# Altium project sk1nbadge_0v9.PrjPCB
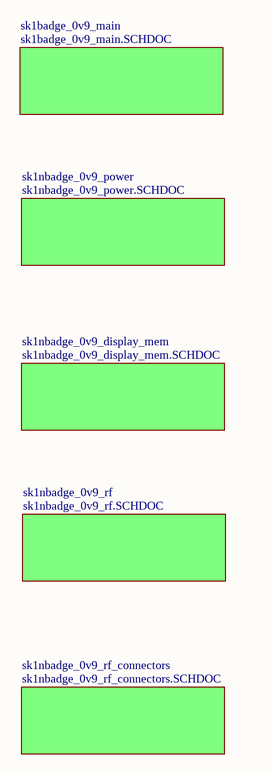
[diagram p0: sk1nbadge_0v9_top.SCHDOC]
6 sheets, 198 parts. Net scope: global (net labels, ports and power ports of the same name join across sheets).
Board file: sk1nbadge_pcb_0v9.pcbdoc
Sheets:
  sk1nbadge_0v9_top.SCHDOC
    sk1badge_0v9_main = sk1badge_0v9_main.SCHDOC
    sk1nbadge_0v9_power = sk1nbadge_0v9_power.SCHDOC
    sk1nbadge_0v9_display_mem = sk1nbadge_0v9_display_mem.SCHDOC
    sk1nbadge_0v9_rf = sk1nbadge_0v9_rf.SCHDOC
    sk1nbadge_0v9_rf_connectors = sk1nbadge_0v9_rf_connectors.SCHDOC

## Sheet sk1nbadge_0v9_top.SCHDOC
size Letter

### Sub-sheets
sk1badge_0v9_main = sk1badge_0v9_main.SCHDOC: no entries
sk1nbadge_0v9_display_mem = sk1nbadge_0v9_display_mem.SCHDOC: no entries
sk1nbadge_0v9_power = sk1nbadge_0v9_power.SCHDOC: no entries
sk1nbadge_0v9_rf = sk1nbadge_0v9_rf.SCHDOC: no entries
sk1nbadge_0v9_rf_connectors = sk1nbadge_0v9_rf_connectors.SCHDOC: no entries

## Sheet sk1badge_0v9_main.SCHDOC
size Letter
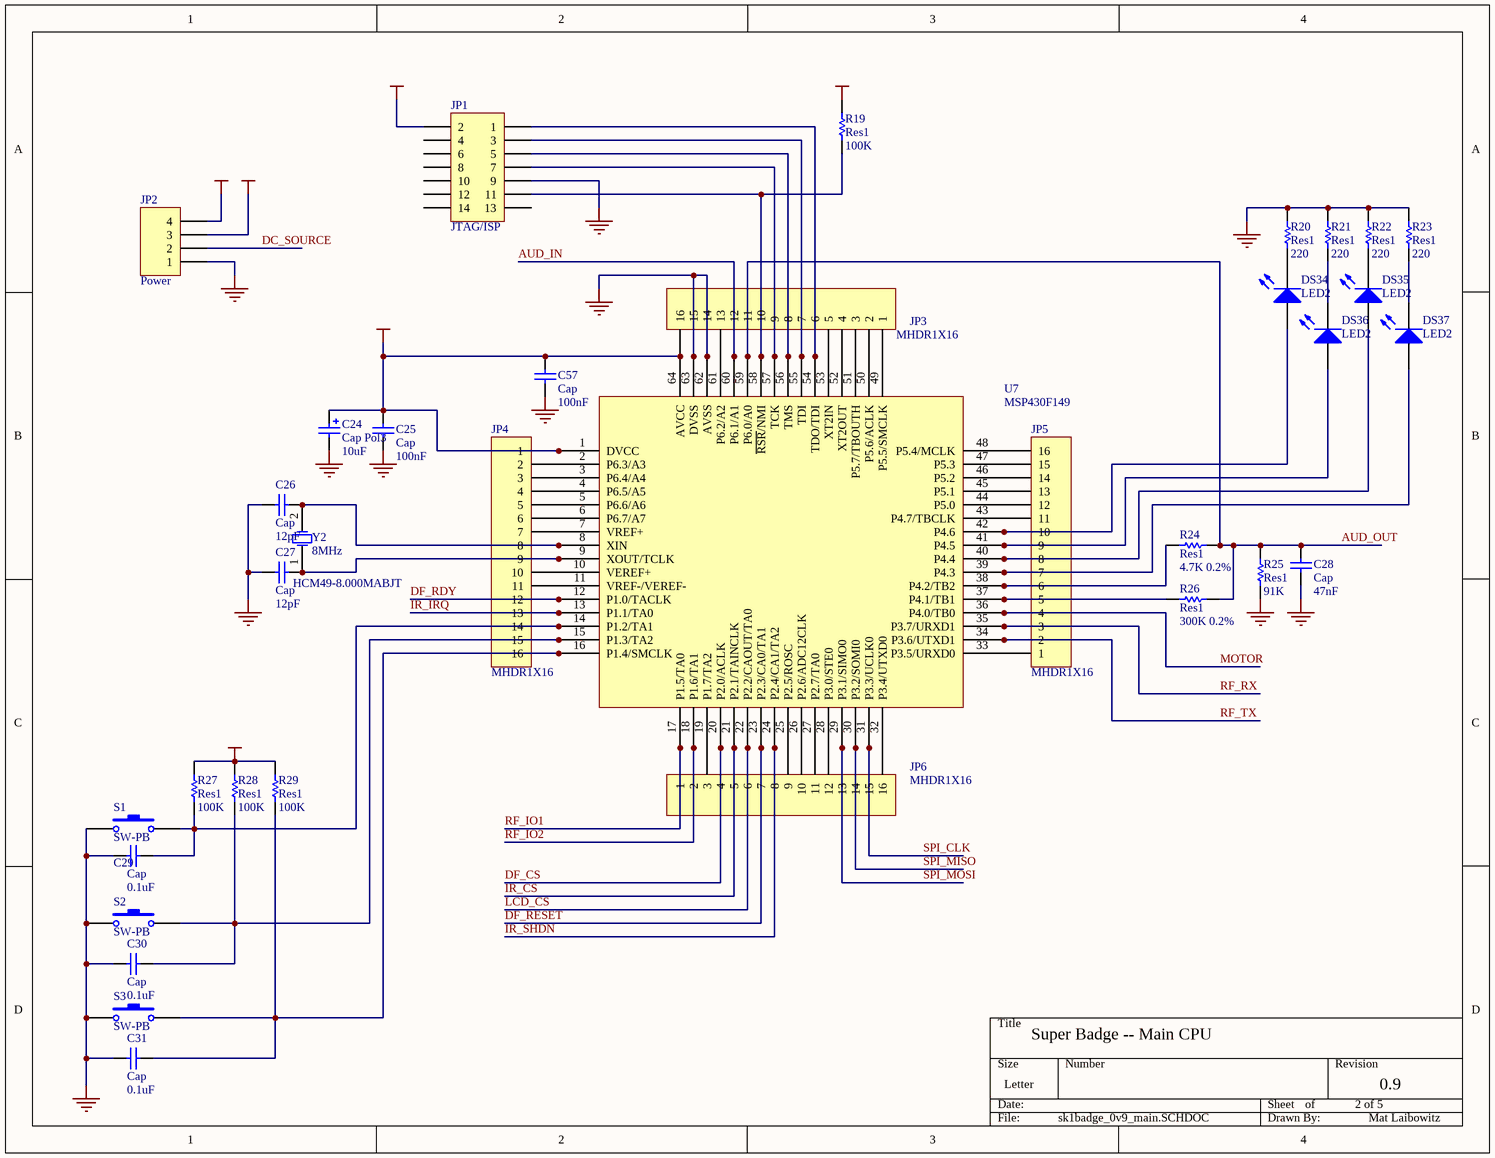
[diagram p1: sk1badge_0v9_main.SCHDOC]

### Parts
C24  Cap Pol3  value 10uF  [6032-28]
C25  Cap  value 100nF  [0402]
C26  Cap  value 12pF  [0402]
C27  Cap  value 12pF  [0402]
C28  Cap  value 47nF  [0402]
C29  Cap  value 0.1uF  [0402]
C30  Cap  value 0.1uF  [0402]
C31  Cap  value 0.1uF  [0402]
C57  Cap  value 100nF  [0402]
DS34  LED2  [LED-1206]
DS35  LED2  [LED-1206]
DS36  LED2  [LED-1206]
DS37  LED2  [LED-1206]
JP1  JTAG/ISP  [HDR2X7]
JP2  Power  [HDR1X4]
JP3  MHDR1X16  [MHDR1X16]
JP4  MHDR1X16  [MHDR1X16]
JP5  MHDR1X16  [MHDR1X16]
JP6  MHDR1X16  [MHDR1X16]
R19  Res1  value 100K  [0402]
R20  Res1  value 220  [0402]
R21  Res1  value 220  [0402]
R22  Res1  value 220  [0402]
R23  Res1  value 220  [0402]
R24  Res1  value 4.7K 0.2%  [0402]
R25  Res1  value 91K  [0402]
R26  Res1  value 300K 0.2%  [0402]
R27  Res1  value 100K  [0402]
R28  Res1  value 100K  [0402]
R29  Res1  value 100K  [0402]
S1  SW-PB  [B3S-1000]
S2  SW-PB  [B3S-1000]
S3  SW-PB  [B3S-1000]
U7  MSP430F149  [QFP64]
Y2  8MHz  PART: HCM49-8.000MABJT  [HCM49]

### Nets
3.3V: C24.1 C25.1 C57.1 JP1.2 JP2.3 JP3.16 JP4.1 R19.2 R27.2 R28.2 R29.2 U7.1(DVCC) U7.64(AVCC)
5V: JP2.4
GND: C24.2 C25.2 C26.1 C27.1 C28.1 C29.1 C30.1 C31.1 C57.2 JP1.9 JP2.1 JP3.14 JP3.15 R20.2 R21.2 R22.2 R23.2 R25.1 S1.1 S2.1 S3.1 U7.62(AVSS) U7.63(DVSS)
AUD_IN: JP3.12 U7.60(P6.1/A1)
AUD_OUT: C28.2 JP3.11 R24.2 R25.2 R26.2 U7.59(P6.0/A0)
DC_SOURCE: JP2.2
DF_CS: JP6.4 U7.20(P2.0/ACLK)
DF_RDY: JP4.12 U7.12(P1.0/TACLK)
DF_RESET: JP6.7 U7.23(P2.3/CA0/TA1)
IR_CS: JP6.5 U7.21(P2.1/TAINCLK)
IR_IRQ: JP4.13 U7.13(P1.1/TA0)
IR_SHDN: JP6.8 U7.24(P2.4/CA1/TA2)
LCD_CS: JP6.6 U7.22(P2.2/CAOUT/TA0)
MOTOR: JP5.4 U7.36(P4.0/TB0)
RF_IO1: JP6.1 U7.17(P1.5/TA0)
RF_IO2: JP6.2 U7.18(P1.6/TA1)
RF_RX: JP5.3 U7.35(P3.7/URXD1)
RF_TX: JP5.2 U7.34(P3.6/UTXD1)
SPI_CLK: JP6.15 U7.31(P3.3/UCLK0)
SPI_MISO: JP6.14 U7.30(P3.2/SOMI0)
SPI_MOSI: JP6.13 U7.29(P3.1/SIMO0)
NetC26_2: C26.2 JP4.8 U7.8(XIN) Y2.2(OSC2)
NetC27_2: C27.2 JP4.9 U7.9(XOUT/TCLK) Y2.1(OSC1)
NetC29_2: C29.2 JP4.14 R27.1 S1.2 U7.14(P1.2/TA1)
NetC30_2: C30.2 JP4.15 R28.1 S2.2 U7.15(P1.3/TA2)
NetC31_2: C31.2 JP4.16 R29.1 S3.2 U7.16(P1.4/SMCLK)
NetDS34_1: DS34.1(A) JP5.10 U7.42(P4.6)
NetDS34_2: DS34.2(K) R20.1
NetDS35_1: DS35.1(A) JP5.8 U7.40(P4.4)
NetDS35_2: DS35.2(K) R22.1
NetDS36_1: DS36.1(A) JP5.9 U7.41(P4.5)
NetDS36_2: DS36.2(K) R21.1
NetDS37_1: DS37.1(A) JP5.7 U7.39(P4.3)
NetDS37_2: DS37.2(K) R23.1
NetJP1_1: JP1.1 JP3.6 U7.54(TDO/TDI)
NetJP1_3: JP1.3 JP3.7 U7.55(TDI)
NetJP1_5: JP1.5 JP3.8 U7.56(TMS)
NetJP1_7: JP1.7 JP3.9 U7.57(TCK)
NetJP1_11: JP1.11 JP3.10 R19.1 U7.58(~{RSR}/NMI)
NetJP3_1: JP3.1 U7.49(P5.5/SMCLK)
NetJP3_2: JP3.2 U7.50(P5.6/ACLK)
NetJP3_3: JP3.3 U7.51(P5.7/TBOUTH)
NetJP3_4: JP3.4 U7.52(XT2OUT)
NetJP3_5: JP3.5 U7.53(XT2IN)
NetJP3_13: JP3.13 U7.61(P6.2/A2)
NetJP4_2: JP4.2 U7.2(P6.3/A3)
NetJP4_3: JP4.3 U7.3(P6.4/A4)
NetJP4_4: JP4.4 U7.4(P6.5/A5)
NetJP4_5: JP4.5 U7.5(P6.6/A6)
NetJP4_6: JP4.6 U7.6(P6.7/A7)
NetJP4_7: JP4.7 U7.7(VREF+)
NetJP4_10: JP4.10 U7.10(VEREF+)
NetJP4_11: JP4.11 U7.11(VREF-/VEREF-)
NetJP5_1: JP5.1 U7.33(P3.5/URXD0)
NetJP5_5: JP5.5 R26.1 U7.37(P4.1/TB1)
NetJP5_6: JP5.6 R24.1 U7.38(P4.2/TB2)
NetJP5_11: JP5.11 U7.43(P4.7/TBCLK)
NetJP5_12: JP5.12 U7.44(P5.0)
NetJP5_13: JP5.13 U7.45(P5.1)
NetJP5_14: JP5.14 U7.46(P5.2)
NetJP5_15: JP5.15 U7.47(P5.3)
NetJP5_16: JP5.16 U7.48(P5.4/MCLK)
NetJP6_3: JP6.3 U7.19(P1.7/TA2)
NetJP6_9: JP6.9 U7.25(P2.5/ROSC)
NetJP6_10: JP6.10 U7.26(P2.6/ADC12CLK)
NetJP6_11: JP6.11 U7.27(P2.7/TA0)
NetJP6_12: JP6.12 U7.28(P3.0/STE0)
NetJP6_16: JP6.16 U7.32(P3.4/UTXD0)

Not connected (* = marked no-connect by the designer): JP1 4 6 8 10 12 13 14

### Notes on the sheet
- Super Badge -- Main CPU
- 2 of 5
- 0.9
- Mat Laibowitz

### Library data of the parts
C24 = Cap Pol3: Polarized Capacitor (Surface Mount); Manufacturer: Generic Components; Class I: Passive
C25-C31 C57 = Cap: Capacitor; Manufacturer: Generic Components; Class I: Passive
DS34-DS37 = LED2: Typical RED, GREEN, YELLOW, AMBER GaAs LED; Manufacturer: Generic Components; Class I: Optoelectronic
JP1 = Header 7X2: Header, 7-Pin, Dual row; Manufacturer: Generic Components; Class I: Connector
JP2 = Header 4: Header, 4-Pin; Manufacturer: Generic Components; Class I: Connector
JP3-JP6 = MHDR1X16: Header, 16-Pin; Manufacturer: Generic Components; Class I: Connector
R19-R29 = Res1: Resistor; Manufacturer: Generic Components; Class I: Passive
S1-S3 = SW-PB: Switch; Manufacturer: Generic Components
Y2 = XTAL: Crystal Oscillator; Manufacturer: Generic Components

## Sheet sk1nbadge_0v9_power.SCHDOC: sk1n Badge -- Power and Audio Sections
size Letter; DrawnBy: Mat Laibowitz; SheetNumber: 3; SheetTotal: 5
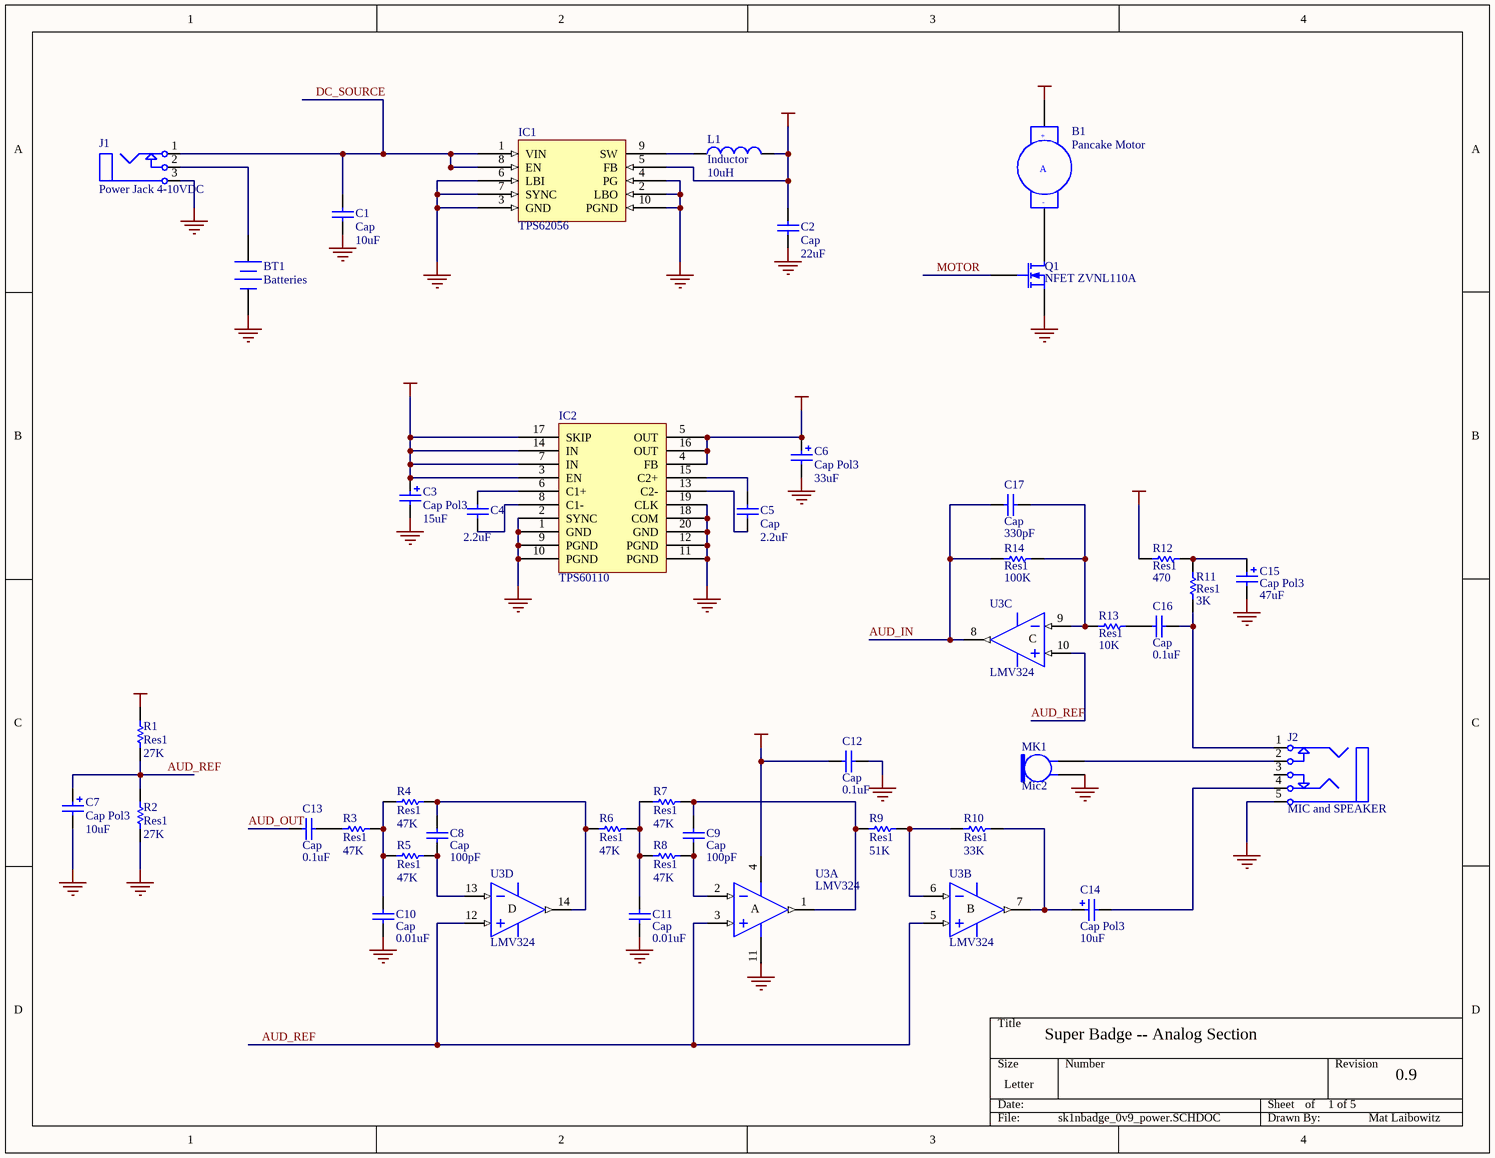
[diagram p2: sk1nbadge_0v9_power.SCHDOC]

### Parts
B1  Pancake Motor  [PANCAKE_MOTOR]
BT1  Batteries  [BAT-2]
C1  Cap  value 10uF  [6032-28]
C2  Cap  value 22uF  [6032-28]
C3  Cap Pol3  value 15uF  [6032-28]
C4  value 2.2uF  [1206]
C5  Cap  value 2.2uF  [1206]
C6  Cap Pol3  value 33uF  [6032-28]
C7  Cap Pol3  value 10uF  [6032-28]
C8  Cap  value 100pF  [0402]
C9  Cap  value 100pF  [0402]
C10  Cap  value 0.01uF  [0402]
C11  Cap  value 0.01uF  [0402]
C12  Cap  value 0.1uF  [0402]
C13  Cap  value 0.1uF  [0402]
C14  Cap Pol3  value 10uF  [6032-28]
C15  Cap Pol3  value 47uF  [6032-28]
C16  Cap  value 0.1uF  [0402]
C17  Cap  value 330pF  [0402]
IC1  (no value)  [MSOP10]
IC2  TPS60110  [TSOP/PWP/20]
J1  Power Jack 4-10VDC  [PJ-002A]
J2  MIC and SPEAKER  [SJ-3535N]
L1  Inductor  value 10uH  [DN4835]
MK1  Mic2  [MIC54B]
Q1  NFET ZVNL110A  [BCY-W3/H.8]
R1  Res1  value 27K  [0402]
R2  Res1  value 27K  [0402]
R3  Res1  value 47K  [0402]
R4  Res1  value 47K  [0402]
R5  Res1  value 47K  [0402]
R6  Res1  value 47K  [0402]
R7  Res1  value 47K  [0402]
R8  Res1  value 47K  [0402]
R9  Res1  value 51K  [0402]
R10  Res1  value 33K  [0402]
R11  Res1  value 3K  [0402]
R12  Res1  value 470  [0402]
R13  Res1  value 10K  [0402]
R14  Res1  value 100K  [0402]
U3  LMV324  [TSSOP14]  (parts A,B,C,D of 4)

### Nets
3.3V: B1.1(+) C2.2 C3.1 C12.1 IC1.5(FB) IC2.3(EN) IC2.7(IN) IC2.14(IN) IC2.17(SKIP) L1.2 R1.2 R12.1 U3.4(V+)
5V: C6.1 IC2.4(FB) IC2.5(OUT) IC2.16(OUT)
GND: BT1.2(-) C1.1 C2.1 C3.2 C6.2 C7.2 C10.1 C11.1 C12.2 C15.2 IC1.2(LBO) IC1.3(GND) IC1.4(PG) IC1.6(LBI) IC1.7(SYNC) IC1.10(PGND) IC2.1(GND) IC2.2(SYNC) IC2.9(PGND) IC2.10(PGND) IC2.11(PGND) IC2.12(PGND) IC2.18(COM) IC2.19(CLK) IC2.20(GND) J1.3(C) J2.5(E) MK1.1 Q1.3(S) R2.1 U3.11(V-)
AUD_IN: C17.1 R14.1 U3.8(OUT)
AUD_OUT: C13.1
AUD_REF: C7.1 R1.1 R2.2 U3.3(IN+) U3.5(IN+) U3.10(IN+) U3.12(IN+)
DC_SOURCE: C1.2 IC1.1(VIN) IC1.8(EN) J1.1(A)
MOTOR: Q1.2(G)
NetB1_2: B1.2(-) Q1.1(D)
NetBT1_1: BT1.1(+) J1.2(B)
NetC4_1: C4.1 IC2.6(C1+)
NetC4_2: C4.2 IC2.8(C1-)
NetC5_1: C5.1 IC2.13(C2-)
NetC5_2: C5.2 IC2.15(C2+)
NetC8_1: C8.1 R5.2 U3.13(IN-)
NetC8_2: C8.2 R4.2 R6.1 U3.14(OUT)
NetC9_1: C9.1 R8.2 U3.2(IN-)
NetC9_2: C9.2 R7.2 R9.1 U3.1(OUT)
NetC10_2: C10.2 R3.2 R4.1 R5.1
NetC11_2: C11.2 R6.2 R7.1 R8.1
NetC13_2: C13.2 R3.1
NetC14_1: C14.1 R10.2 U3.7(OUT)
NetC14_2: C14.2 J2.4(D)
NetC15_1: C15.1 R11.2 R12.2
NetC16_1: C16.1 R13.2
NetC16_2: C16.2 J2.1(A) R11.1
NetC17_2: C17.2 R13.1 R14.2 U3.9(IN-)
NetIC1_9: IC1.9(SW) L1.1
NetJ2_2: J2.2(B) MK1.2
NetR9_2: R9.2 R10.1 U3.6(IN-)

Not connected (* = marked no-connect by the designer): J2 3(C)

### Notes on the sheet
- Super Badge -- Analog Section
- 1 of 5
- 0.9
- Mat Laibowitz

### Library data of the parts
B1 = Motor Servo: Servo Motor; Manufacturer: Generic Components
BT1 = Battery: Multicell Battery; Manufacturer: Generic Components
C1 C2 C4 C5 C8-C13 C16 C17 = Cap: as C25 on sheet sk1badge_0v9_main
C3 C6 C7 C14 C15 = Cap Pol3: as C24 on sheet sk1badge_0v9_main
IC1 = TPS62056: TI STEP DOWN CONVERTER
IC2 = TPS60110: TI CHARGE PUMP DC/DC CONVERTER
J1 = Phonejack: 2-Conductor Jack with 1 break contact; Manufacturer: Generic Components; Class I: Connector
J2 = Phonejack Stero SW: 3-Conductor Jack with 2 break contacts (normals) and 1 auxiliary make contact; Manufacturer: Generic Components; Class I: Connector
L1 = Inductor: Manufacturer: Generic Components; Class I: Passive
MK1 = Mic2: Microphone; Manufacturer: Generic Components
Q1 = MOSFET-N: N-Channel MOSFET; Manufacturer: Generic Components; Class I: Discrete; Class II: MOSFET - Low Power
R1-R14 = Res1: as R19 on sheet sk1badge_0v9_main
U3 = LMV324: Quad Low Voltage Op Amp; Manufacturer: Analog Devices; Class I: Amplifier; Class II: Operational Amplifier

## Sheet sk1nbadge_0v9_display_mem.SCHDOC
size Letter
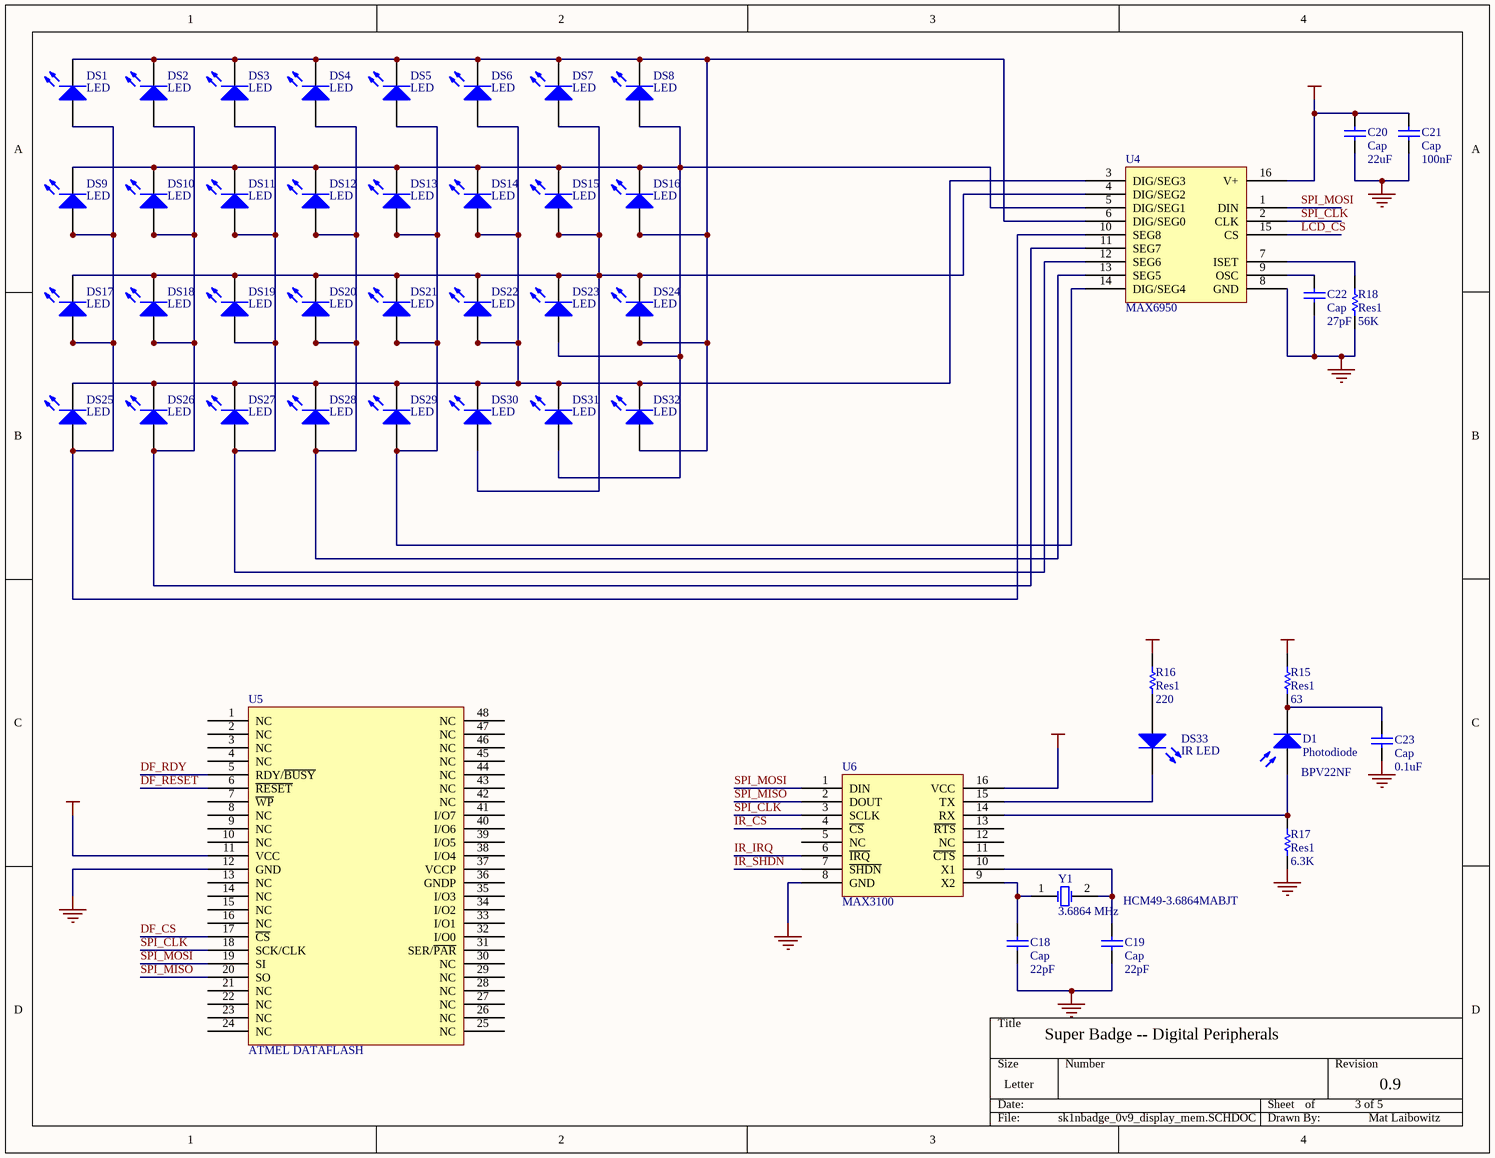
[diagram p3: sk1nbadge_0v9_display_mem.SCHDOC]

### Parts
C18  Cap  value 22pF  [0402]
C19  Cap  value 22pF  [0402]
C20  Cap  value 22uF  [1206]
C21  Cap  value 100nF  [0402]
C22  Cap  value 27pF  [0402]
C23  Cap  value 0.1uF  [0402]
D1  Photodiode  PART: BPV22NF  [PIN2]
DS1  LED  [LED-1206]
DS2  LED  [LED-1206]
DS3  LED  [LED-1206]
DS4  LED  [LED-1206]
DS5  LED  [LED-1206]
DS6  LED  [LED-1206]
DS7  LED  [LED-1206]
DS8  LED  [LED-1206]
DS9  LED  [LED-1206]
DS10  LED  [LED-1206]
DS11  LED  [LED-1206]
DS12  LED  [LED-1206]
DS13  LED  [LED-1206]
DS14  LED  [LED-1206]
DS15  LED  [LED-1206]
DS16  LED  [LED-1206]
DS17  LED  [LED-1206]
DS18  LED  [LED-1206]
DS19  LED  [LED-1206]
DS20  LED  [LED-1206]
DS21  LED  [LED-1206]
DS22  LED  [LED-1206]
DS23  LED  [LED-1206]
DS24  LED  [LED-1206]
DS25  LED  [LED-1206]
DS26  LED  [LED-1206]
DS27  LED  [LED-1206]
DS28  LED  [LED-1206]
DS29  LED  [LED-1206]
DS30  LED  [LED-1206]
DS31  LED  [LED-1206]
DS32  LED  [LED-1206]
DS33  IR LED  [PIN2]
R15  Res1  value 63  [0402]
R16  Res1  value 220  [0402]
R17  Res1  value 6.3K  [0402]
R18  Res1  value 56K  [0402]
U4  MAX6950  [QSOP16]
U5  ATMEL DATAFLASH  [TSSOP48/DF]
U6  MAX3100  [QSOP16]
Y1  3.6864 MHz  PART: HCM49-3.6864MABJT  [HCM49]

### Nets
3.3V: C20.2 C21.2 R15.2 R16.2 U4.16(V+) U5.11(VCC) U6.16(VCC)
GND: C18.1 C19.1 C20.1 C21.1 C22.1 C23.1 R17.1 R18.1 U4.8(GND) U5.12(GND) U6.8(GND)
DF_CS: U5.17(~{CS})
DF_RDY: U5.5(RDY/~{BUSY})
DF_RESET: U5.6(~{RESET})
IR_CS: U6.4(~{CS})
IR_IRQ: U6.6(~{IRQ})
IR_SHDN: U6.7(~{SHDN})
LCD_CS: U4.15(CS)
SPI_CLK: U4.2(CLK) U5.18(SCK/CLK) U6.3(SCLK)
SPI_MISO: U5.20(SO) U6.2(DOUT)
SPI_MOSI: U4.1(DIN) U5.19(SI) U6.1(DIN)
NetC18_2: C18.2 U6.9(X2) Y1.1(OSC1)
NetC19_2: C19.2 U6.10(X1) Y1.2(OSC2)
NetC22_2: C22.2 U4.9(OSC)
NetC23_2: C23.2 D1.2(K) R15.1
NetD1_1: D1.1(A) R17.2 U6.14(RX)
NetDS1_1: DS1.1(A) DS9.1(A) DS17.1(A) DS25.1(A) U4.10(SEG8)
NetDS1_2: DS1.2(K) DS2.2(K) DS3.2(K) DS4.2(K) DS5.2(K) DS6.2(K) DS7.2(K) DS8.2(K) DS16.1(A) DS24.1(A) DS32.1(A) U4.6(DIG/SEG0)
NetDS2_1: DS2.1(A) DS10.1(A) DS18.1(A) DS26.1(A) U4.11(SEG7)
NetDS3_1: DS3.1(A) DS11.1(A) DS19.1(A) DS27.1(A) U4.12(SEG6)
NetDS4_1: DS4.1(A) DS12.1(A) DS20.1(A) DS28.1(A) U4.13(SEG5)
NetDS5_1: DS5.1(A) DS13.1(A) DS21.1(A) DS29.1(A) U4.14(DIG/SEG4)
NetDS6_1: DS6.1(A) DS14.1(A) DS22.1(A) DS25.2(K) DS26.2(K) DS27.2(K) DS28.2(K) DS29.2(K) DS30.2(K) DS31.2(K) DS32.2(K) U4.3(DIG/SEG3)
NetDS7_1: DS7.1(A) DS15.1(A) DS17.2(K) DS18.2(K) DS19.2(K) DS20.2(K) DS21.2(K) DS22.2(K) DS23.2(K) DS24.2(K) DS30.1(A) U4.4(DIG/SEG2)
NetDS8_1: DS8.1(A) DS9.2(K) DS10.2(K) DS11.2(K) DS12.2(K) DS13.2(K) DS14.2(K) DS15.2(K) DS16.2(K) DS23.1(A) DS31.1(A) U4.5(DIG/SEG1)
NetDS33_1: DS33.1(A) R16.1
NetDS33_2: DS33.2(K) U6.15(TX)
NetR18_2: R18.2 U4.7(ISET)

Not connected (* = marked no-connect by the designer): U5 1(NC) 2(NC) 3(NC) 4(NC) 7(~{WP}) 8(NC) 9(NC) 10(NC) 13(NC) 14(NC) 15(NC) 16(NC) 21(NC) 22(NC) 23(NC) 24(NC) 25(NC) 26(NC) 27(NC) 28(NC) 29(NC) 30(NC) 31(SER/~{PAR}) 32(I/O0) 33(I/O1) 34(I/O2) 35(I/O3) 36(GNDP) 37(VCCP) 38(I/O4) 39(I/O5) 40(I/O6) 41(I/O7) 42(NC) 43(NC) 44(NC) 45(NC) 46(NC) 47(NC) 48(NC); U6 5(NC) 11(~{CTS}) 12(NC) 13(~{RTS})

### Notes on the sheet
- Super Badge -- Digital Peripherals
- 3 of 5
- 0.9
- Mat Laibowitz

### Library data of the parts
C18-C23 = Cap: as C25 on sheet sk1badge_0v9_main
D1 = Photo Sen: Photosensitive Diode; Manufacturer: Generic Components; Class I: Optoelectronic
DS1-DS33 = LED2: as DS34 on sheet sk1badge_0v9_main
R15-R18 = Res1: as R19 on sheet sk1badge_0v9_main
Y1 = XTAL: as Y2 on sheet sk1badge_0v9_main

## Sheet sk1nbadge_0v9_rf.SCHDOC
size Letter
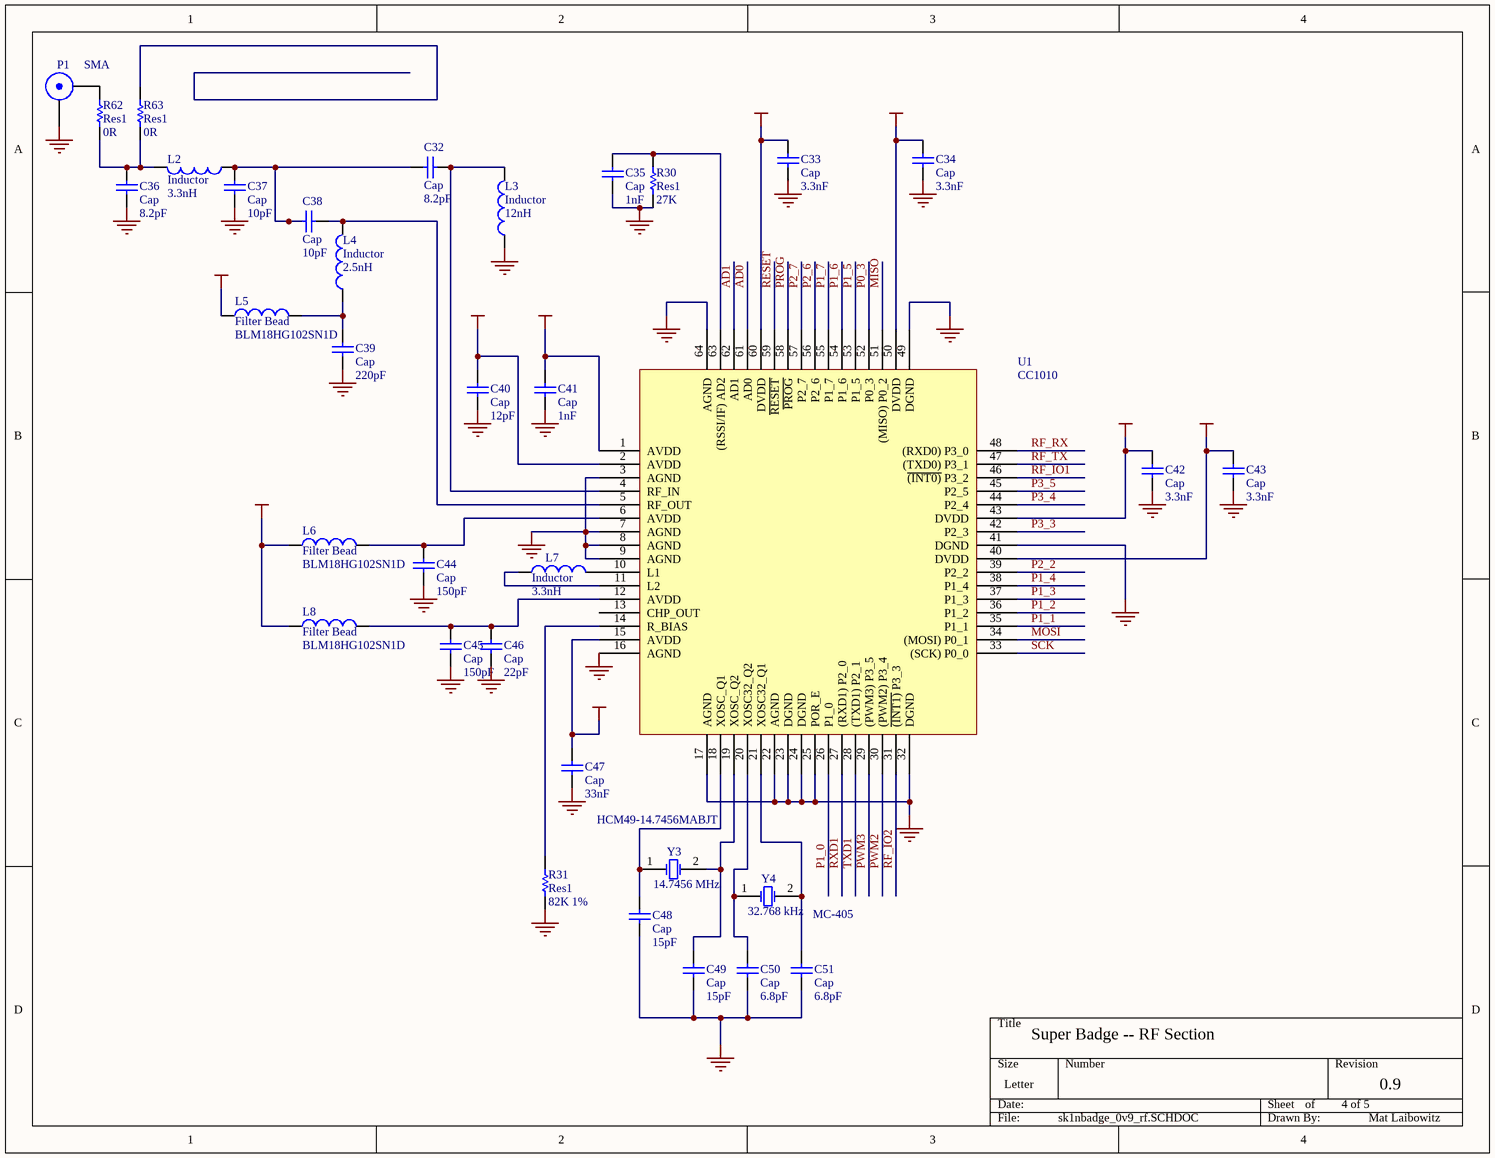
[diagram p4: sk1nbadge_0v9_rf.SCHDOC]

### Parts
C32  Cap  value 8.2pF  [0402]
C33  Cap  value 3.3nF  [0402]
C34  Cap  value 3.3nF  [0402]
C35  Cap  value 1nF  [0402]
C36  Cap  value 8.2pF  [0402]
C37  Cap  value 10pF  [0402]
C38  Cap  value 10pF  [0402]
C39  Cap  value 220pF  [0402]
C40  Cap  value 12pF  [0402]
C41  Cap  value 1nF  [0402]
C42  Cap  value 3.3nF  [0402]
C43  Cap  value 3.3nF  [0402]
C44  Cap  value 150pF  [0402]
C45  Cap  value 150pF  [0402]
C46  Cap  value 22pF  [0402]
C47  Cap  value 33nF  [0402]
C48  Cap  value 15pF  [0402]
C49  Cap  value 15pF  [0402]
C50  Cap  value 6.8pF  [0402]
C51  Cap  value 6.8pF  [0402]
L2  Inductor  value 3.3nH  [0603]
L3  Inductor  value 12nH  [0603]
L4  Inductor  value 2.5nH  [C1005-0402]
L5  Filter Bead  PART: BLM18HG102SN1D  [0603]
L6  Filter Bead  PART: BLM18HG102SN1D  [0603]
L7  Inductor  value 3.3nH  [0603]
L8  Filter Bead  PART: BLM18HG102SN1D  [0603]
P1  SMA  [SMA/SM]
R30  Res1  value 27K  [0402]
R31  Res1  value 82K 1%  [0402]
R62  Res1  value 0R  [0402]
R63  Res1  value 0R  [0402]
U1  CC1010  [TQFP64]
Y3  14.7456 MHz  PART: HCM49-14.7456MABJT  [HCM49]
Y4  32.768 kHz  [MC-405]

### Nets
3.3V: C33.2 C34.2 C40.2 C41.2 C42.2 C43.2 C47.2 L5.1 L6.1 L8.1 U1.1(AVDD) U1.2(AVDD) U1.15(AVDD) U1.40(DVDD) U1.43(DVDD) U1.50(DVDD) U1.60(DVDD)
GND: C33.1 C34.1 C35.1 C36.1 C37.1 C39.1 C40.1 C41.1 C42.1 C43.1 C44.1 C45.1 C46.1 C47.1 C48.2 C49.1 C50.1 C51.1 L3.1 P1.2(Y) R30.1 R31.1 U1.3(AGND) U1.7(AGND) U1.8(AGND) U1.9(AGND) U1.16(AGND) U1.17(AGND) U1.22(AGND) U1.23(DGND) U1.24(DGND) U1.25(POR_E) U1.32(DGND) U1.41(DGND) U1.49(DGND) U1.64(AGND)
AD0: U1.61(AD0)
AD1: U1.62(AD1)
MISO: U1.51((MISO)_P0_2)
MOSI: U1.34((MOSI)_P0_1)
P0_3: U1.52(P0_3)
P1_0: U1.26(P1_0)
P1_1: U1.35(P1_1)
P1_2: U1.36(P1_2)
P1_3: U1.37(P1_3)
P1_4: U1.38(P1_4)
P1_5: U1.53(P1_5)
P1_6: U1.54(P1_6)
P1_7: U1.55(P1_7)
P2_2: U1.39(P2_2)
P2_6: U1.56(P2_6)
P2_7: U1.57(P2_7)
P3_3: U1.42(P2_3)
P3_4: U1.44(P2_4)
P3_5: U1.45(P2_5)
PROG: U1.58(~{PROG})
PWM2: U1.30((PWM2)_P3_4)
PWM3: U1.29((PWM3)_P3_5)
RESET: U1.59(~{RESET})
RF_IO1: U1.46(~{(INT0)}_P3_2)
RF_IO2: U1.31(~{(INT1)}_P3_3)
RF_RX: U1.48((RXD0)_P3_0)
RF_TX: U1.47((TXD0)_P3_1)
RXD1: U1.27((RXD1)_P2_0)
SCK: U1.33((SCK)_P0_0)
TXD1: U1.28((TXD1)_P2_1)
NetC32_1: C32.1 C37.2 C38.1 L2.1
NetC32_2: C32.2 L3.2 U1.4(RF_IN)
NetC35_2: C35.2 R30.2 U1.63((RSSI/IF)_AD2)
NetC36_2: C36.2 L2.2 R62.1 R63.1
NetC38_2: C38.2 L4.2 U1.5(RF_OUT)
NetC39_2: C39.2 L4.1 L5.2
NetC44_2: C44.2 L6.2 U1.6(AVDD)
NetC45_2: C45.2 C46.2 L8.2 U1.12(AVDD)
NetC48_1: C48.1 U1.18(XOSC_Q1) Y3.1(OSC1)
NetC49_2: C49.2 U1.19(XOSC_Q2) Y3.2(OSC2)
NetC50_2: C50.2 U1.20(XOSC32_Q2) Y4.1(OSC1)
NetC51_2: C51.2 U1.21(XOSC32_Q1) Y4.2(OSC2)
NetL7_1: L7.1 U1.11(L2)
NetL7_2: L7.2 U1.10(L1)
NetP1_1: P1.1(X) R62.2
NetR31_2: R31.2 U1.14(R_BIAS)

Not connected (* = marked no-connect by the designer): R63 2; U1 13(CHP_OUT)

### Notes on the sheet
- Super Badge -- RF Section
- 4 of 5
- 0.9
- Mat Laibowitz

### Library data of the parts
C32-C51 = Cap: as C25 on sheet sk1badge_0v9_main
L2-L4 L7 = Inductor: as L1 on sheet sk1nbadge_0v9_power
L5 L6 L8 = Inductor: Manufacturer: Generic Components; Class I: Passive; Value: 10mH
P1 = SMA: SMA Straight Connector; Manufacturer: Generic Components; Class II: RF Coaxial
R30 R31 R62 R63 = Res1: as R19 on sheet sk1badge_0v9_main
Y3 Y4 = XTAL: as Y2 on sheet sk1badge_0v9_main

## Sheet sk1nbadge_0v9_rf_connectors.SCHDOC
size Letter
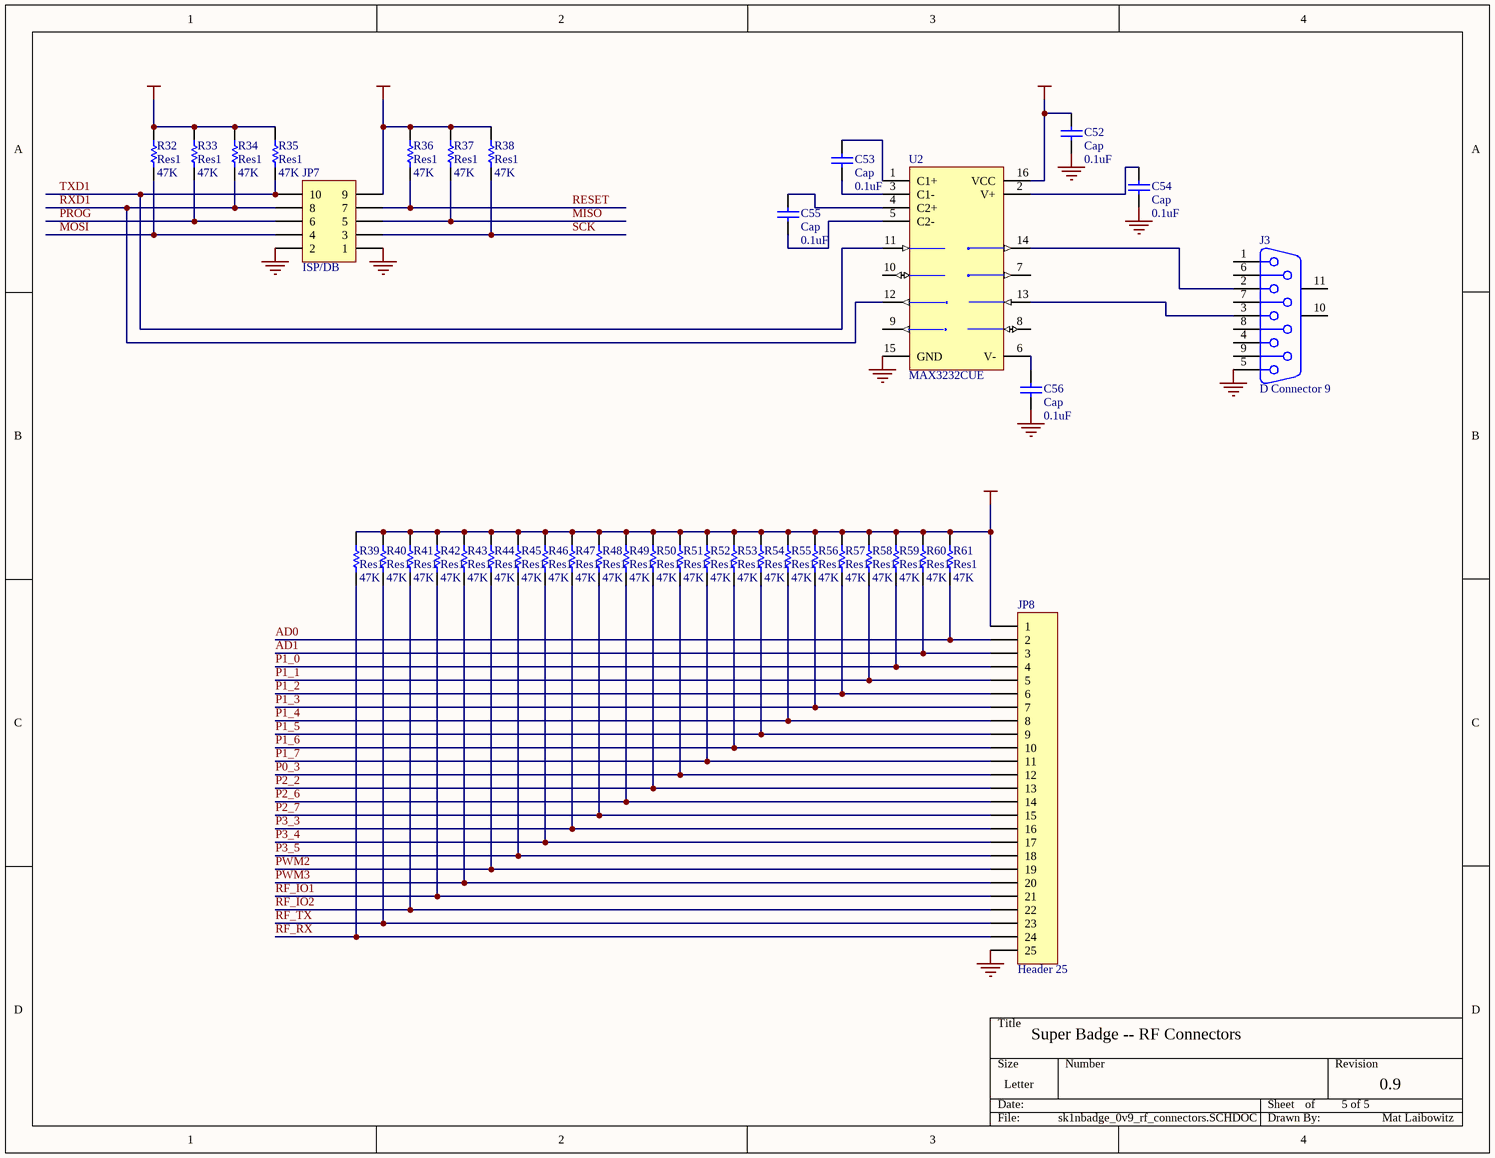
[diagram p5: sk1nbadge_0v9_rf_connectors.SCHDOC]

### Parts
C52  Cap  value 0.1uF  [0402]
C53  Cap  value 0.1uF  [0402]
C54  Cap  value 0.1uF  [0402]
C55  Cap  value 0.1uF  [0402]
C56  Cap  value 0.1uF  [0402]
J3  D Connector 9  [DSUB1.385-2H9]
JP7  ISP/DB  [HDR2X5]
JP8  Header 25  [HDR1X25]
R32  Res1  value 47K  [0402]
R33  Res1  value 47K  [0402]
R34  Res1  value 47K  [0402]
R35  Res1  value 47K  [0402]
R36  Res1  value 47K  [0402]
R37  Res1  value 47K  [0402]
R38  Res1  value 47K  [0402]
R39  Res1  value 47K  [0402]
R40  Res1  value 47K  [0402]
R41  Res1  value 47K  [0402]
R42  Res1  value 47K  [0402]
R43  Res1  value 47K  [0402]
R44  Res1  value 47K  [0402]
R45  Res1  value 47K  [0402]
R46  Res1  value 47K  [0402]
R47  Res1  value 47K  [0402]
R48  Res1  value 47K  [0402]
R49  Res1  value 47K  [0402]
R50  Res1  value 47K  [0402]
R51  Res1  value 47K  [0402]
R52  Res1  value 47K  [0402]
R53  Res1  value 47K  [0402]
R54  Res1  value 47K  [0402]
R55  Res1  value 47K  [0402]
R56  Res1  value 47K  [0402]
R57  Res1  value 47K  [0402]
R58  Res1  value 47K  [0402]
R59  Res1  value 47K  [0402]
R60  Res1  value 47K  [0402]
R61  Res1  value 47K  [0402]
U2  MAX3232CUE  [TSSO5x6-G16]

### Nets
3.3V: C52.2 JP7.9 JP8.1 R32.2 R33.2 R34.2 R35.2 R36.2 R37.2 R38.2 R39.2 R40.2 R41.2 R42.2 R43.2 R44.2 R45.2 R46.2 R47.2 R48.2 R49.2 R50.2 R51.2 R52.2 R53.2 R54.2 R55.2 R56.2 R57.2 R58.2 R59.2 R60.2 R61.2 U2.16(VCC)
GND: C52.1 C54.1 C56.1 J3.5 JP7.1 JP7.2 JP8.25 U2.15(GND)
AD0: JP8.2 R61.1
AD1: JP8.3 R60.1
MISO: JP7.5 R37.1
MOSI: JP7.4 R32.1
P0_3: JP8.12 R51.1
P1_0: JP8.4 R59.1
P1_1: JP8.5 R58.1
P1_2: JP8.6 R57.1
P1_3: JP8.7 R56.1
P1_4: JP8.8 R55.1
P1_5: JP8.9 R54.1
P1_6: JP8.10 R53.1
P1_7: JP8.11 R52.1
P2_2: JP8.13 R50.1
P2_6: JP8.14 R49.1
P2_7: JP8.15 R48.1
P3_3: JP8.16 R47.1
P3_4: JP8.17 R46.1
P3_5: JP8.18 R45.1
PROG: JP7.6 R33.1
PWM2: JP8.19 R44.1
PWM3: JP8.20 R43.1
RESET: JP7.7 R36.1
RF_IO1: JP8.21 R42.1
RF_IO2: JP8.22 R41.1
RF_RX: JP8.24 R39.1
RF_TX: JP8.23 R40.1
RXD1: JP7.8 R34.1 U2.12(R1OUT)
SCK: JP7.3 R38.1
TXD1: JP7.10 R35.1 U2.11(T1IN)
NetC53_1: C53.1 U2.3(C1-)
NetC53_2: C53.2 U2.1(C1+)
NetC54_2: C54.2 U2.2(V+)
NetC55_1: C55.1 U2.5(C2-)
NetC55_2: C55.2 U2.4(C2+)
NetC56_2: C56.2 U2.6(V-)
NetJ3_2: J3.2 U2.14(T1OUT)
NetJ3_3: J3.3 U2.13(R1IN)

Not connected (* = marked no-connect by the designer): J3 1 4 6 7 8 9 10(MH1) 11(MH2); U2 7(T2OUT) 8(R2IN) 9(R2OUT) 10(T2IN)

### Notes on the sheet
- Super Badge -- RF Connectors
- 5 of 5
- 0.9
- Mat Laibowitz

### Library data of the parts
C52-C56 = Cap: as C25 on sheet sk1badge_0v9_main
J3 = D Connector 9: Receptacle Assembly, 9 Position, Right Angle; Manufacturer: Generic Components; Package Information: Latest Revision: O; Positions: 9
JP7 = Header 5X2: Header, 5-Pin, Dual row; Manufacturer: Generic Components; Class I: Connector
JP8 = Header 25: Header, 25-Pin; Manufacturer: Generic Components; Class I: Connector
R32-R61 = Res1: as R19 on sheet sk1badge_0v9_main
U2 = MAX3232CUE: 3.0V TO 5.5V, Low-Power, up to 1Mbps, True RS-232 Transceiver Using Four 0.1µF External Capacitor; Manufacturer: Maxim; Package Information: Latest Revision: 21-0066 C; Class I: Communication

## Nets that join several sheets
3.3V: sk1badge_0v9_main (13 pins), sk1nbadge_0v9_power (13 pins), sk1nbadge_0v9_display_mem (7 pins), sk1nbadge_0v9_rf (17 pins), sk1nbadge_0v9_rf_connectors (34 pins)
5V: sk1badge_0v9_main (JP2.4), sk1nbadge_0v9_power (C6.1 IC2.4 IC2.5 IC2.16)
GND: sk1badge_0v9_main (23 pins), sk1nbadge_0v9_power (31 pins), sk1nbadge_0v9_display_mem (11 pins), sk1nbadge_0v9_rf (36 pins), sk1nbadge_0v9_rf_connectors (8 pins)
AD0: sk1nbadge_0v9_rf (U1.61), sk1nbadge_0v9_rf_connectors (JP8.2 R61.1)
AD1: sk1nbadge_0v9_rf (U1.62), sk1nbadge_0v9_rf_connectors (JP8.3 R60.1)
AUD_IN: sk1badge_0v9_main (JP3.12 U7.60), sk1nbadge_0v9_power (C17.1 R14.1 U3.8)
AUD_OUT: sk1badge_0v9_main (6 pins), sk1nbadge_0v9_power (C13.1)
DC_SOURCE: sk1badge_0v9_main (JP2.2), sk1nbadge_0v9_power (C1.2 IC1.1 IC1.8 J1.1)
DF_CS: sk1badge_0v9_main (JP6.4 U7.20), sk1nbadge_0v9_display_mem (U5.17)
DF_RDY: sk1badge_0v9_main (JP4.12 U7.12), sk1nbadge_0v9_display_mem (U5.5)
DF_RESET: sk1badge_0v9_main (JP6.7 U7.23), sk1nbadge_0v9_display_mem (U5.6)
IR_CS: sk1badge_0v9_main (JP6.5 U7.21), sk1nbadge_0v9_display_mem (U6.4)
IR_IRQ: sk1badge_0v9_main (JP4.13 U7.13), sk1nbadge_0v9_display_mem (U6.6)
IR_SHDN: sk1badge_0v9_main (JP6.8 U7.24), sk1nbadge_0v9_display_mem (U6.7)
LCD_CS: sk1badge_0v9_main (JP6.6 U7.22), sk1nbadge_0v9_display_mem (U4.15)
MISO: sk1nbadge_0v9_rf (U1.51), sk1nbadge_0v9_rf_connectors (JP7.5 R37.1)
MOSI: sk1nbadge_0v9_rf (U1.34), sk1nbadge_0v9_rf_connectors (JP7.4 R32.1)
MOTOR: sk1badge_0v9_main (JP5.4 U7.36), sk1nbadge_0v9_power (Q1.2)
P0_3: sk1nbadge_0v9_rf (U1.52), sk1nbadge_0v9_rf_connectors (JP8.12 R51.1)
P1_0: sk1nbadge_0v9_rf (U1.26), sk1nbadge_0v9_rf_connectors (JP8.4 R59.1)
P1_1: sk1nbadge_0v9_rf (U1.35), sk1nbadge_0v9_rf_connectors (JP8.5 R58.1)
P1_2: sk1nbadge_0v9_rf (U1.36), sk1nbadge_0v9_rf_connectors (JP8.6 R57.1)
P1_3: sk1nbadge_0v9_rf (U1.37), sk1nbadge_0v9_rf_connectors (JP8.7 R56.1)
P1_4: sk1nbadge_0v9_rf (U1.38), sk1nbadge_0v9_rf_connectors (JP8.8 R55.1)
P1_5: sk1nbadge_0v9_rf (U1.53), sk1nbadge_0v9_rf_connectors (JP8.9 R54.1)
P1_6: sk1nbadge_0v9_rf (U1.54), sk1nbadge_0v9_rf_connectors (JP8.10 R53.1)
P1_7: sk1nbadge_0v9_rf (U1.55), sk1nbadge_0v9_rf_connectors (JP8.11 R52.1)
P2_2: sk1nbadge_0v9_rf (U1.39), sk1nbadge_0v9_rf_connectors (JP8.13 R50.1)
P2_6: sk1nbadge_0v9_rf (U1.56), sk1nbadge_0v9_rf_connectors (JP8.14 R49.1)
P2_7: sk1nbadge_0v9_rf (U1.57), sk1nbadge_0v9_rf_connectors (JP8.15 R48.1)
P3_3: sk1nbadge_0v9_rf (U1.42), sk1nbadge_0v9_rf_connectors (JP8.16 R47.1)
P3_4: sk1nbadge_0v9_rf (U1.44), sk1nbadge_0v9_rf_connectors (JP8.17 R46.1)
P3_5: sk1nbadge_0v9_rf (U1.45), sk1nbadge_0v9_rf_connectors (JP8.18 R45.1)
PROG: sk1nbadge_0v9_rf (U1.58), sk1nbadge_0v9_rf_connectors (JP7.6 R33.1)
PWM2: sk1nbadge_0v9_rf (U1.30), sk1nbadge_0v9_rf_connectors (JP8.19 R44.1)
PWM3: sk1nbadge_0v9_rf (U1.29), sk1nbadge_0v9_rf_connectors (JP8.20 R43.1)
RESET: sk1nbadge_0v9_rf (U1.59), sk1nbadge_0v9_rf_connectors (JP7.7 R36.1)
RF_IO1: sk1badge_0v9_main (JP6.1 U7.17), sk1nbadge_0v9_rf (U1.46), sk1nbadge_0v9_rf_connectors (JP8.21 R42.1)
RF_IO2: sk1badge_0v9_main (JP6.2 U7.18), sk1nbadge_0v9_rf (U1.31), sk1nbadge_0v9_rf_connectors (JP8.22 R41.1)
RF_RX: sk1badge_0v9_main (JP5.3 U7.35), sk1nbadge_0v9_rf (U1.48), sk1nbadge_0v9_rf_connectors (JP8.24 R39.1)
RF_TX: sk1badge_0v9_main (JP5.2 U7.34), sk1nbadge_0v9_rf (U1.47), sk1nbadge_0v9_rf_connectors (JP8.23 R40.1)
RXD1: sk1nbadge_0v9_rf (U1.27), sk1nbadge_0v9_rf_connectors (JP7.8 R34.1 U2.12)
SCK: sk1nbadge_0v9_rf (U1.33), sk1nbadge_0v9_rf_connectors (JP7.3 R38.1)
SPI_CLK: sk1badge_0v9_main (JP6.15 U7.31), sk1nbadge_0v9_display_mem (U4.2 U5.18 U6.3)
SPI_MISO: sk1badge_0v9_main (JP6.14 U7.30), sk1nbadge_0v9_display_mem (U5.20 U6.2)
SPI_MOSI: sk1badge_0v9_main (JP6.13 U7.29), sk1nbadge_0v9_display_mem (U4.1 U5.19 U6.1)
TXD1: sk1nbadge_0v9_rf (U1.28), sk1nbadge_0v9_rf_connectors (JP7.10 R35.1 U2.11)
